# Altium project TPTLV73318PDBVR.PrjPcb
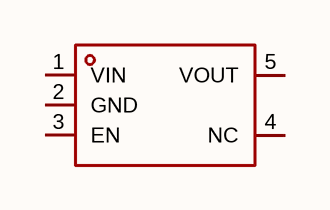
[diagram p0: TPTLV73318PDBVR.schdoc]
1 sheet, 1 parts. Net scope: global (net labels, ports and power ports of the same name join across sheets).

## Sheet TPTLV73318PDBVR.schdoc
size 127 x 101 mm

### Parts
U?  tptlv73318pdbvr  [SOT-23-5_L3.0-W1.7-P0.95-LS2.8-BR]  (value not drawn)

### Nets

Not connected (* = marked no-connect by the designer): U? 1(VIN) 2(GND) 3(EN) 4(NC) 5(VOUT)

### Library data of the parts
U? = tptlv73318pdbvr: 输出极性:正极;工作电压:5.5V;输出电压:1.8V;输出电流:300mA;电源纹波抑制比(PSRR):75dB@(1kHz);输出类型:固定;; Manufacturer: TECH PUBLIC(台舟); AddInBom: yes; ModelId: 0a2a1b8f50944f73965918ad6e5fe167; ModelName: SOT-23-5_L2.9-W1.6-H1.1-LS2.8-P0.95; ModelTransform: 114.173,109.636,0,180,0,0,0,0,0; Output Configuration: 正极; Voltage - Supply: 5.5V; Output Voltage: 1.8V; Output Current: 300mA; Voltage Dropout: 470mV@(300mA); standby current: 15uA; Noise: 48uVrms; Output Type: 固定; Number of Outputs: 1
